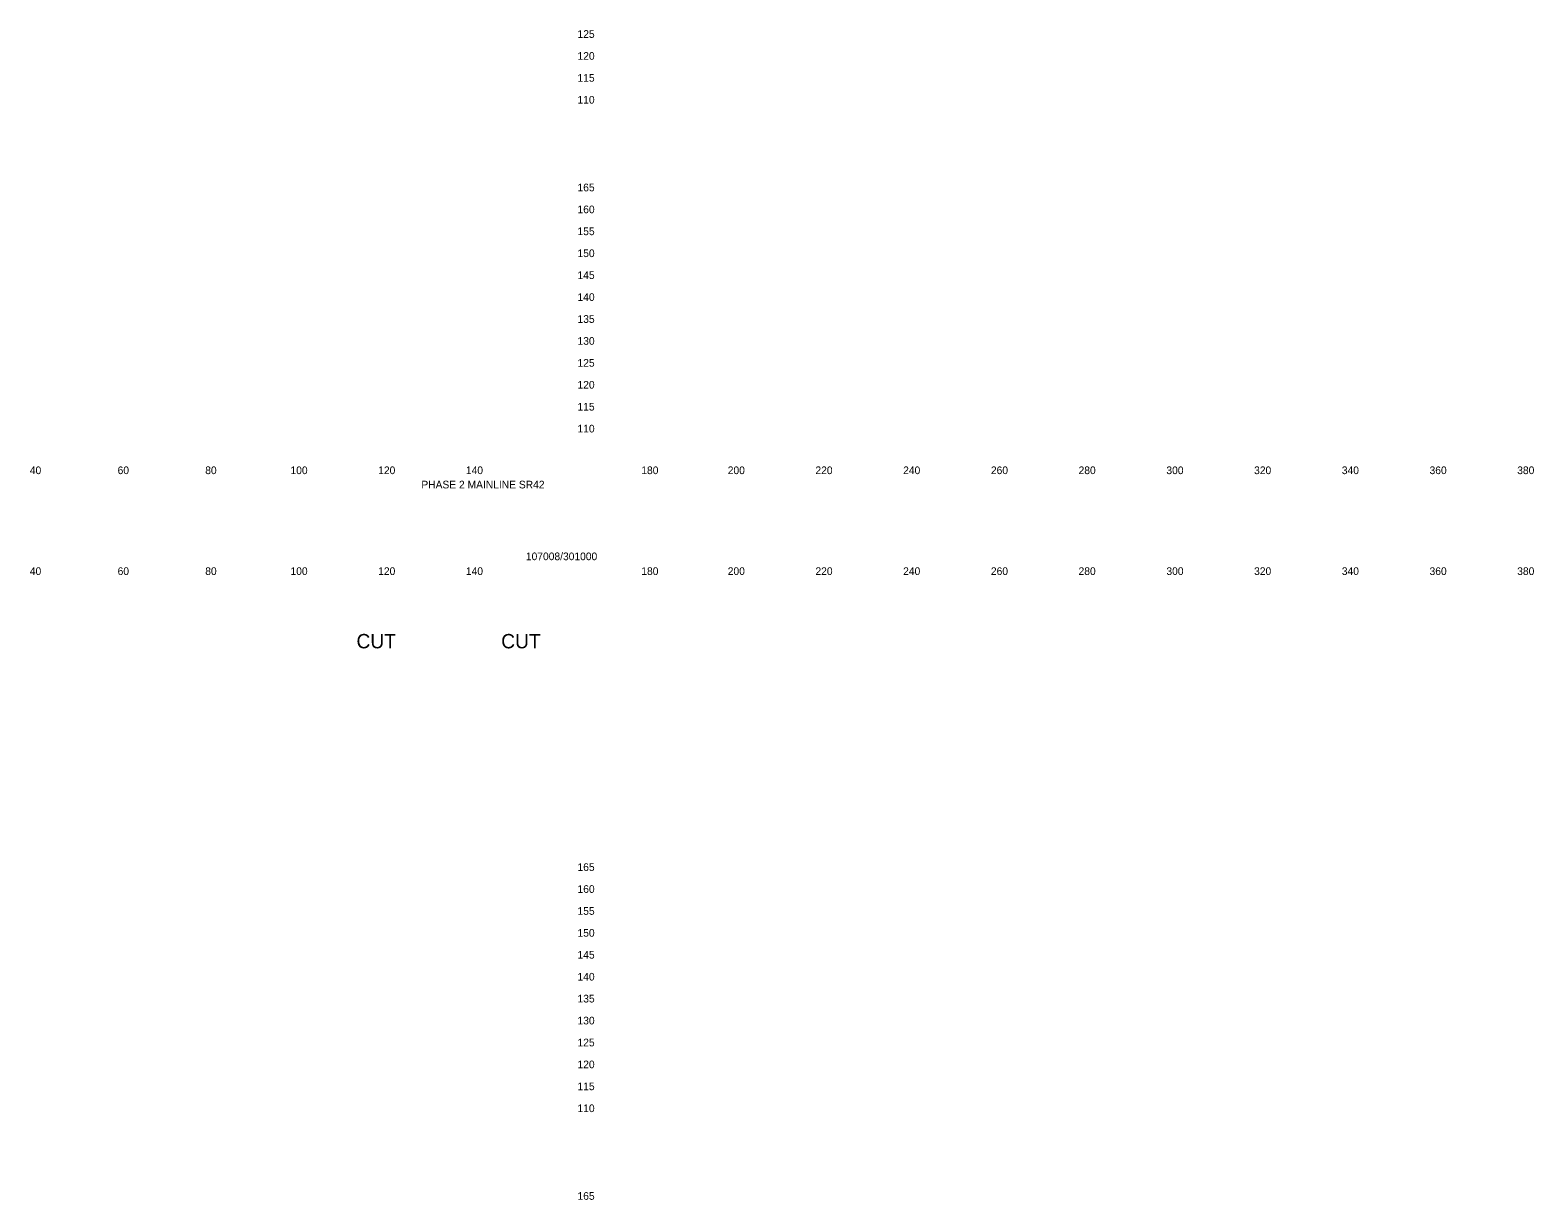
# Model space of a CAD drawing. Extents: x 21281 to 22024, y 6472 to 15208.
# Drawn here: x 21681.3 to 22024.2, y 8379.8 to 8646.6 of the extents above; entities that cross this region are included whole.
import ezdxf

# ---------------------------------------------------------------- set-up
doc = ezdxf.new("R2010")
doc.units = 0
doc.layers.add('XS_SHEET_LABELS_ELEVATION', color=7, linetype='Continuous')
doc.layers.add('XS_SHEET_LABELS_OFFSET', color=7, linetype='Continuous')

msp = doc.modelspace()

# ---------------------------------------------------------------- texts
at = {"layer": 'XS_SHEET_LABELS_ELEVATION'}
for s, p in [('  125  ', (21804.84, 8644.84)), ('  120  ', (21804.84, 8639.84)), ('  115  ', (21804.84, 8634.84)), ('  110  ', (21804.84, 8629.84)), ('  165  ', (21804.84, 8609.84)), ('  160  ', (21804.84, 8604.84)), ('  155  ', (21804.84, 8599.84)), ('  150  ', (21804.84, 8594.84)), ('  145  ', (21804.84, 8589.84)), ('  140  ', (21804.84, 8584.84)), ('  135  ', (21804.84, 8579.84)), ('  130  ', (21804.84, 8574.84)), ('  125  ', (21804.84, 8569.84)), ('  120  ', (21804.84, 8564.84)), ('  115  ', (21804.84, 8559.84)), ('  110  ', (21804.84, 8554.84)), ('  165  ', (21804.84, 8454.84)), ('  160  ', (21804.84, 8449.84)), ('  155  ', (21804.84, 8444.84)), ('  150  ', (21804.84, 8439.84)), ('  145  ', (21804.84, 8434.84)), ('  140  ', (21804.84, 8429.84)), ('  135  ', (21804.84, 8424.84)), ('  130  ', (21804.84, 8419.84)), ('  125  ', (21804.84, 8414.84)), ('  120  ', (21804.84, 8409.84)), ('  115  ', (21804.84, 8404.84)), ('  110  ', (21804.84, 8399.84)), ('  165  ', (21804.84, 8379.84))]:
    msp.add_text(s, height=1.75, dxfattribs=at).set_placement(p)
at = {"layer": 'XS_SHEET_LABELS_OFFSET'}
for s, height, p in [('  40  ', 1.75, (21679.95, 8545.34)), ('  60  ', 1.75, (21699.97, 8545.34)), ('  80  ', 1.75, (21719.95, 8545.34)), ('  100  ', 1.75, (21739.39, 8545.34)), ('  120  ', 1.75, (21759.39, 8545.34)), ('  140  ', 1.75, (21779.39, 8545.34)), ('  180  ', 1.75, (21819.39, 8545.34)), ('  200  ', 1.75, (21839.1, 8545.34)), ('  220  ', 1.75, (21859.1, 8545.34)), ('  240  ', 1.75, (21879.1, 8545.34)), ('  260  ', 1.75, (21899.11, 8545.34)), ('  280  ', 1.75, (21919.1, 8545.34)), ('  300  ', 1.75, (21939.13, 8545.34)), ('  320  ', 1.75, (21959.13, 8545.34)), ('  340  ', 1.75, (21979.13, 8545.34)), ('  360  ', 1.75, (21999.14, 8545.34)), ('  380  ', 1.75, (22019.13, 8545.34)), ('PHASE 2 MAINLINE SR42', 1.75, (21770.53, 8542.08)), ('107008/301000', 1.75, (21794.37, 8525.71)), ('  40  ', 1.75, (21679.95, 8522.34)), ('  60  ', 1.75, (21699.97, 8522.34)), ('  80  ', 1.75, (21719.95, 8522.34)), ('  100  ', 1.75, (21739.39, 8522.34)), ('  120  ', 1.75, (21759.39, 8522.34)), ('  140  ', 1.75, (21779.39, 8522.34)), ('  180  ', 1.75, (21819.39, 8522.34)), ('  200  ', 1.75, (21839.1, 8522.34)), ('  220  ', 1.75, (21859.1, 8522.34)), ('  240  ', 1.75, (21879.1, 8522.34)), ('  260  ', 1.75, (21899.11, 8522.34)), ('  280  ', 1.75, (21919.1, 8522.34)), ('  300  ', 1.75, (21939.13, 8522.34)), ('  320  ', 1.75, (21959.13, 8522.34)), ('  340  ', 1.75, (21979.13, 8522.34)), ('  360  ', 1.75, (21999.14, 8522.34)), ('  380  ', 1.75, (22019.13, 8522.34)), ('CUT', 3.273, (21755.74, 8505.61)), ('CUT', 3.273, (21788.74, 8505.61))]:
    msp.add_text(s, height=height, dxfattribs=at).set_placement(p)

doc.saveas('drawing.dxf')
